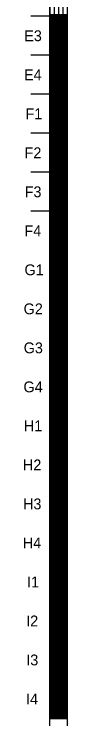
# Model space of a CAD drawing. Extents: x -124 to 80, y -10800 to 19.
# Drawn here: x -120 to 80, y -6482 to -3230 of the extents above; entities that cross this region are included whole.
import ezdxf

# ---------------------------------------------------------------- set-up
doc = ezdxf.new("R2010")
doc.units = 0
for name, color, linetype in [('Scratch_Level_1', 7, 'Continuous'), ('Scratch_Level_3', 7, 'Continuous'), ('Sheet Clip Boundary CELL', 7, 'Continuous')]:
    doc.layers.add(name, color=color, linetype=linetype)

msp = doc.modelspace()

# ---------------------------------------------------------------- linework, layer by layer
at = {"layer": 'Scratch_Level_1'}
for p, q in [((0, 0), (0, -6480)), ((20, 0), (20, -6480)), ((40, 0), (40, -6480)), ((60, 0), (60, -6480)), ((80, 0), (80, -6480)), ((0, -3240), (-88.8, -3240)), ((0, -3232), (80, -3232)), ((0, -3236), (80, -3236)), ((0, -3240), (80, -3240)), ((0, -3244), (80, -3244)), ((0, -3248), (80, -3248)), ((0, -3252), (80, -3252)), ((0, -3256), (80, -3256)), ((0, -3260), (80, -3260)), ((0, -3264), (80, -3264)), ((0, -3268), (80, -3268)), ((0, -3272), (80, -3272)), ((0, -3276), (80, -3276)), ((0, -3280), (80, -3280)), ((0, -3284), (80, -3284)), ((0, -3288), (80, -3288)), ((0, -3292), (80, -3292)), ((0, -3296), (80, -3296)), ((0, -3300), (80, -3300)), ((0, -3304), (80, -3304)), ((0, -3308), (80, -3308)), ((0, -3312), (80, -3312)), ((0, -3316), (80, -3316)), ((0, -3320), (80, -3320)), ((0, -3324), (80, -3324)), ((0, -3328), (80, -3328)), ((0, -3332), (80, -3332)), ((0, -3336), (80, -3336)), ((0, -3340), (80, -3340)), ((0, -3344), (80, -3344)), ((0, -3348), (80, -3348)), ((0, -3352), (80, -3352)), ((0, -3356), (80, -3356)), ((0, -3360), (80, -3360)), ((0, -3364), (80, -3364)), ((0, -3368), (80, -3368)), ((0, -3372), (80, -3372)), ((0, -3376), (80, -3376)), ((0, -3380), (80, -3380)), ((0, -3384), (80, -3384)), ((0, -3388), (80, -3388)), ((0, -3392), (80, -3392)), ((0, -3396), (80, -3396)), ((0, -3400), (80, -3400)), ((0, -3404), (80, -3404)), ((0, -3408), (80, -3408)), ((0, -3412), (80, -3412)), ((0, -3420), (-88.8, -3420)), ((0, -3416), (80, -3416)), ((0, -3420), (80, -3420)), ((0, -3424), (80, -3424)), ((0, -3428), (80, -3428)), ((0, -3432), (80, -3432)), ((0, -3436), (80, -3436)), ((0, -3440), (80, -3440)), ((0, -3444), (80, -3444)), ((0, -3448), (80, -3448)), ((0, -3452), (80, -3452)), ((0, -3456), (80, -3456)), ((0, -3460), (80, -3460)), ((0, -3464), (80, -3464)), ((0, -3468), (80, -3468)), ((0, -3472), (80, -3472)), ((0, -3476), (80, -3476)), ((0, -3480), (80, -3480)), ((0, -3484), (80, -3484)), ((0, -3488), (80, -3488)), ((0, -3492), (80, -3492)), ((0, -3496), (80, -3496)), ((0, -3500), (80, -3500)), ((0, -3504), (80, -3504)), ((0, -3508), (80, -3508)), ((0, -3512), (80, -3512)), ((0, -3516), (80, -3516)), ((0, -3520), (80, -3520)), ((0, -3524), (80, -3524)), ((0, -3528), (80, -3528)), ((0, -3532), (80, -3532)), ((0, -3536), (80, -3536)), ((0, -3540), (80, -3540)), ((0, -3544), (80, -3544)), ((0, -3548), (80, -3548)), ((0, -3552), (80, -3552)), ((0, -3556), (80, -3556)), ((0, -3560), (80, -3560)), ((0, -3564), (80, -3564)), ((0, -3568), (80, -3568)), ((0, -3572), (80, -3572)), ((0, -3576), (80, -3576)), ((0, -3600), (-88.8, -3600)), ((0, -3580), (80, -3580)), ((0, -3584), (80, -3584)), ((0, -3588), (80, -3588)), ((0, -3592), (80, -3592)), ((0, -3596), (80, -3596)), ((0, -3600), (80, -3600)), ((0, -3604), (80, -3604)), ((0, -3608), (80, -3608)), ((0, -3612), (80, -3612)), ((0, -3616), (80, -3616)), ((0, -3620), (80, -3620)), ((0, -3624), (80, -3624)), ((0, -3628), (80, -3628)), ((0, -3632), (80, -3632)), ((0, -3636), (80, -3636)), ((0, -3640), (80, -3640)), ((0, -3644), (80, -3644)), ((0, -3648), (80, -3648)), ((0, -3652), (80, -3652)), ((0, -3656), (80, -3656)), ((0, -3660), (80, -3660)), ((0, -3664), (80, -3664)), ((0, -3668), (80, -3668)), ((0, -3672), (80, -3672)), ((0, -3676), (80, -3676)), ((0, -3680), (80, -3680)), ((0, -3684), (80, -3684)), ((0, -3688), (80, -3688)), ((0, -3692), (80, -3692)), ((0, -3696), (80, -3696)), ((0, -3700), (80, -3700)), ((0, -3704), (80, -3704)), ((0, -3708), (80, -3708)), ((0, -3712), (80, -3712)), ((0, -3716), (80, -3716)), ((0, -3720), (80, -3720)), ((0, -3724), (80, -3724)), ((0, -3728), (80, -3728)), ((0, -3732), (80, -3732)), ((0, -3736), (80, -3736)), ((0, -3740), (80, -3740)), ((0, -3744), (80, -3744)), ((0, -3748), (80, -3748)), ((0, -3752), (80, -3752)), ((0, -3756), (80, -3756)), ((0, -3760), (80, -3760)), ((0, -3764), (80, -3764)), ((0, -3768), (80, -3768)), ((0, -3772), (80, -3772)), ((0, -3780), (-88.8, -3780)), ((0, -3776), (80, -3776)), ((0, -3780), (80, -3780)), ((0, -3784), (80, -3784)), ((0, -3788), (80, -3788)), ((0, -3792), (80, -3792)), ((0, -3796), (80, -3796)), ((0, -3800), (80, -3800)), ((0, -3804), (80, -3804)), ((0, -3808), (80, -3808)), ((0, -3812), (80, -3812)), ((0, -3816), (80, -3816)), ((0, -3820), (80, -3820)), ((0, -3824), (80, -3824)), ((0, -3828), (80, -3828)), ((0, -3832), (80, -3832)), ((0, -3836), (80, -3836)), ((0, -3840), (80, -3840)), ((0, -3844), (80, -3844)), ((0, -3848), (80, -3848)), ((0, -3852), (80, -3852)), ((0, -3856), (80, -3856)), ((0, -3860), (80, -3860)), ((0, -3864), (80, -3864)), ((0, -3868), (80, -3868)), ((0, -3872), (80, -3872)), ((0, -3876), (80, -3876)), ((0, -3880), (80, -3880)), ((0, -3884), (80, -3884)), ((0, -3888), (80, -3888)), ((0, -3892), (80, -3892)), ((0, -3896), (80, -3896)), ((0, -3900), (80, -3900)), ((0, -3904), (80, -3904)), ((0, -3908), (80, -3908)), ((0, -3912), (80, -3912)), ((0, -3916), (80, -3916)), ((0, -3920), (80, -3920)), ((0, -3924), (80, -3924)), ((0, -3928), (80, -3928)), ((0, -3932), (80, -3932)), ((0, -3960), (-88.8, -3960)), ((0, -3936), (80, -3936)), ((0, -3940), (80, -3940)), ((0, -3944), (80, -3944)), ((0, -3948), (80, -3948)), ((0, -3952), (80, -3952)), ((0, -3956), (80, -3956)), ((0, -3960), (80, -3960)), ((0, -3964), (80, -3964)), ((0, -3968), (80, -3968)), ((0, -3972), (80, -3972)), ((0, -3976), (80, -3976)), ((0, -3980), (80, -3980)), ((0, -3984), (80, -3984)), ((0, -3988), (80, -3988)), ((0, -3992), (80, -3992)), ((0, -3996), (80, -3996)), ((0, -4000), (80, -4000)), ((0, -4004), (80, -4004)), ((0, -4008), (80, -4008)), ((0, -4012), (80, -4012)), ((0, -4016), (80, -4016)), ((0, -4020), (80, -4020)), ((0, -4024), (80, -4024)), ((0, -4028), (80, -4028)), ((0, -4032), (80, -4032)), ((0, -4036), (80, -4036)), ((0, -4040), (80, -4040)), ((0, -4044), (80, -4044)), ((0, -4048), (80, -4048)), ((0, -4052), (80, -4052)), ((0, -4056), (80, -4056)), ((0, -4060), (80, -4060)), ((0, -4064), (80, -4064)), ((0, -4068), (80, -4068)), ((0, -4072), (80, -4072)), ((0, -4076), (80, -4076)), ((0, -4080), (80, -4080)), ((0, -4084), (80, -4084)), ((0, -4088), (80, -4088)), ((0, -4092), (80, -4092)), ((0, -4096), (80, -4096)), ((0, -4100), (80, -4100)), ((0, -4104), (80, -4104)), ((0, -4108), (80, -4108)), ((0, -4112), (80, -4112)), ((0, -4116), (80, -4116)), ((0, -4120), (80, -4120)), ((0, -4124), (80, -4124)), ((0, -4128), (80, -4128)), ((0, -4140), (-88.8, -4140)), ((0, -4132), (80, -4132)), ((0, -4136), (80, -4136)), ((0, -4140), (80, -4140)), ((0, -4144), (80, -4144)), ((0, -4148), (80, -4148)), ((0, -4152), (80, -4152)), ((0, -4156), (80, -4156)), ((0, -4160), (80, -4160)), ((0, -4164), (80, -4164)), ((0, -4168), (80, -4168)), ((0, -4172), (80, -4172)), ((0, -4176), (80, -4176)), ((0, -4180), (80, -4180)), ((0, -4184), (80, -4184)), ((0, -4188), (80, -4188)), ((0, -4192), (80, -4192)), ((0, -4196), (80, -4196)), ((0, -4200), (80, -4200)), ((0, -4204), (80, -4204)), ((0, -4208), (80, -4208)), ((0, -4212), (80, -4212)), ((0, -4216), (80, -4216)), ((0, -4220), (80, -4220)), ((0, -4224), (80, -4224)), ((0, -4228), (80, -4228)), ((0, -4232), (80, -4232)), ((0, -4236), (80, -4236)), ((0, -4240), (80, -4240)), ((0, -4244), (80, -4244)), ((0, -4248), (80, -4248)), ((0, -4252), (80, -4252)), ((0, -4256), (80, -4256)), ((0, -4260), (80, -4260)), ((0, -4264), (80, -4264)), ((0, -4268), (80, -4268)), ((0, -4272), (80, -4272)), ((0, -4276), (80, -4276)), ((0, -4280), (80, -4280)), ((0, -4284), (80, -4284)), ((0, -4288), (80, -4288)), ((0, -4292), (80, -4292)), ((0, -4296), (80, -4296)), ((0, -4300), (80, -4300)), ((0, -4304), (80, -4304)), ((0, -4308), (80, -4308)), ((0, -4312), (80, -4312)), ((0, -4316), (80, -4316)), ((0, -4320), (80, -4320)), ((0, -4324), (80, -4324)), ((0, -4328), (80, -4328)), ((0, -4332), (80, -4332)), ((0, -4336), (80, -4336)), ((0, -4340), (80, -4340)), ((0, -4344), (80, -4344)), ((0, -4348), (80, -4348)), ((0, -4352), (80, -4352)), ((0, -4356), (80, -4356)), ((0, -4360), (80, -4360)), ((0, -4364), (80, -4364)), ((0, -4368), (80, -4368)), ((0, -4372), (80, -4372)), ((0, -4376), (80, -4376)), ((0, -4380), (80, -4380)), ((0, -4384), (80, -4384)), ((0, -4388), (80, -4388)), ((0, -4392), (80, -4392)), ((0, -4396), (80, -4396)), ((0, -4400), (80, -4400)), ((0, -4404), (80, -4404)), ((0, -4408), (80, -4408)), ((0, -4412), (80, -4412)), ((0, -4416), (80, -4416)), ((0, -4420), (80, -4420)), ((0, -4424), (80, -4424)), ((0, -4428), (80, -4428)), ((0, -4432), (80, -4432)), ((0, -4436), (80, -4436)), ((0, -4440), (80, -4440)), ((0, -4444), (80, -4444)), ((0, -4448), (80, -4448)), ((0, -4452), (80, -4452)), ((0, -4456), (80, -4456)), ((0, -4460), (80, -4460)), ((0, -4464), (80, -4464)), ((0, -4468), (80, -4468)), ((0, -4472), (80, -4472)), ((0, -4476), (80, -4476)), ((0, -4480), (80, -4480)), ((0, -4484), (80, -4484)), ((0, -4488), (80, -4488)), ((0, -4492), (80, -4492)), ((0, -4496), (80, -4496)), ((0, -4500), (80, -4500)), ((0, -4504), (80, -4504)), ((0, -4508), (80, -4508)), ((0, -4512), (80, -4512)), ((0, -4516), (80, -4516)), ((0, -4520), (80, -4520)), ((0, -4524), (80, -4524)), ((0, -4528), (80, -4528)), ((0, -4532), (80, -4532)), ((0, -4536), (80, -4536)), ((0, -4540), (80, -4540)), ((0, -4544), (80, -4544)), ((0, -4548), (80, -4548)), ((0, -4552), (80, -4552)), ((0, -4556), (80, -4556)), ((0, -4560), (80, -4560)), ((0, -4564), (80, -4564)), ((0, -4568), (80, -4568)), ((0, -4572), (80, -4572)), ((0, -4576), (80, -4576)), ((0, -4580), (80, -4580)), ((0, -4584), (80, -4584)), ((0, -4588), (80, -4588)), ((0, -4592), (80, -4592)), ((0, -4596), (80, -4596)), ((0, -4600), (80, -4600)), ((0, -4604), (80, -4604)), ((0, -4608), (80, -4608)), ((0, -4612), (80, -4612)), ((0, -4616), (80, -4616)), ((0, -4620), (80, -4620)), ((0, -4624), (80, -4624)), ((0, -4628), (80, -4628)), ((0, -4632), (80, -4632)), ((0, -4636), (80, -4636)), ((0, -4640), (80, -4640)), ((0, -4644), (80, -4644)), ((0, -4648), (80, -4648)), ((0, -4652), (80, -4652)), ((0, -4656), (80, -4656)), ((0, -4660), (80, -4660)), ((0, -4664), (80, -4664)), ((0, -4668), (80, -4668)), ((0, -4672), (80, -4672)), ((0, -4676), (80, -4676)), ((0, -4680), (80, -4680)), ((0, -4684), (80, -4684)), ((0, -4688), (80, -4688)), ((0, -4692), (80, -4692)), ((0, -4696), (80, -4696)), ((0, -4700), (80, -4700)), ((0, -4704), (80, -4704)), ((0, -4708), (80, -4708)), ((0, -4712), (80, -4712)), ((0, -4716), (80, -4716)), ((0, -4720), (80, -4720)), ((0, -4724), (80, -4724)), ((0, -4728), (80, -4728)), ((0, -4732), (80, -4732)), ((0, -4736), (80, -4736)), ((0, -4740), (80, -4740)), ((0, -4744), (80, -4744)), ((0, -4748), (80, -4748)), ((0, -4752), (80, -4752)), ((0, -4756), (80, -4756)), ((0, -4760), (80, -4760)), ((0, -4764), (80, -4764)), ((0, -4768), (80, -4768)), ((0, -4772), (80, -4772)), ((0, -4776), (80, -4776)), ((0, -4780), (80, -4780)), ((0, -4784), (80, -4784)), ((0, -4788), (80, -4788)), ((0, -4792), (80, -4792)), ((0, -4796), (80, -4796)), ((0, -4800), (80, -4800)), ((0, -4804), (80, -4804)), ((0, -4808), (80, -4808)), ((0, -4812), (80, -4812)), ((0, -4816), (80, -4816)), ((0, -4820), (80, -4820)), ((0, -4824), (80, -4824)), ((0, -4828), (80, -4828)), ((0, -4832), (80, -4832)), ((0, -4836), (80, -4836)), ((0, -4840), (80, -4840)), ((0, -4844), (80, -4844)), ((0, -4848), (80, -4848)), ((0, -4852), (80, -4852)), ((0, -4856), (80, -4856)), ((0, -4860), (80, -4860)), ((0, -4864), (80, -4864)), ((0, -4868), (80, -4868)), ((0, -4872), (80, -4872)), ((0, -4876), (80, -4876)), ((0, -4880), (80, -4880)), ((0, -4884), (80, -4884)), ((0, -4888), (80, -4888)), ((0, -4892), (80, -4892)), ((0, -4896), (80, -4896)), ((0, -4900), (80, -4900)), ((0, -4904), (80, -4904)), ((0, -4908), (80, -4908)), ((0, -4912), (80, -4912)), ((0, -4916), (80, -4916)), ((0, -4920), (80, -4920)), ((0, -4924), (80, -4924)), ((0, -4928), (80, -4928)), ((0, -4932), (80, -4932)), ((0, -4936), (80, -4936)), ((0, -4940), (80, -4940)), ((0, -4944), (80, -4944)), ((0, -4948), (80, -4948)), ((0, -4952), (80, -4952)), ((0, -4956), (80, -4956)), ((0, -4960), (80, -4960)), ((0, -4964), (80, -4964)), ((0, -4968), (80, -4968)), ((0, -4972), (80, -4972)), ((0, -4976), (80, -4976)), ((0, -4980), (80, -4980)), ((0, -4984), (80, -4984)), ((0, -4988), (80, -4988)), ((0, -4992), (80, -4992)), ((0, -4996), (80, -4996)), ((0, -5000), (80, -5000)), ((0, -5004), (80, -5004)), ((0, -5008), (80, -5008)), ((0, -5012), (80, -5012)), ((0, -5016), (80, -5016)), ((0, -5020), (80, -5020)), ((0, -5024), (80, -5024)), ((0, -5028), (80, -5028)), ((0, -5032), (80, -5032)), ((0, -5036), (80, -5036)), ((0, -5040), (80, -5040)), ((0, -5044), (80, -5044)), ((0, -5048), (80, -5048)), ((0, -5052), (80, -5052)), ((0, -5056), (80, -5056)), ((0, -5060), (80, -5060)), ((0, -5064), (80, -5064)), ((0, -5068), (80, -5068)), ((0, -5072), (80, -5072)), ((0, -5076), (80, -5076)), ((0, -5080), (80, -5080)), ((0, -5084), (80, -5084)), ((0, -5088), (80, -5088)), ((0, -5092), (80, -5092)), ((0, -5096), (80, -5096)), ((0, -5100), (80, -5100)), ((0, -5104), (80, -5104)), ((0, -5108), (80, -5108)), ((0, -5112), (80, -5112)), ((0, -5116), (80, -5116)), ((0, -5120), (80, -5120)), ((0, -5124), (80, -5124)), ((0, -5128), (80, -5128)), ((0, -5132), (80, -5132)), ((0, -5136), (80, -5136)), ((0, -5140), (80, -5140)), ((0, -5144), (80, -5144)), ((0, -5148), (80, -5148)), ((0, -5152), (80, -5152)), ((0, -5156), (80, -5156)), ((0, -5160), (80, -5160)), ((0, -5164), (80, -5164)), ((0, -5168), (80, -5168)), ((0, -5172), (80, -5172)), ((0, -5176), (80, -5176)), ((0, -5180), (80, -5180)), ((0, -5184), (80, -5184)), ((0, -5188), (80, -5188)), ((0, -5192), (80, -5192)), ((0, -5196), (80, -5196)), ((0, -5200), (80, -5200)), ((0, -5204), (80, -5204)), ((0, -5208), (80, -5208)), ((0, -5212), (80, -5212)), ((0, -5216), (80, -5216)), ((0, -5220), (80, -5220)), ((0, -5224), (80, -5224)), ((0, -5228), (80, -5228)), ((0, -5232), (80, -5232)), ((0, -5236), (80, -5236)), ((0, -5240), (80, -5240)), ((0, -5244), (80, -5244)), ((0, -5248), (80, -5248)), ((0, -5252), (80, -5252)), ((0, -5256), (80, -5256)), ((0, -5260), (80, -5260)), ((0, -5264), (80, -5264)), ((0, -5268), (80, -5268)), ((0, -5272), (80, -5272)), ((0, -5276), (80, -5276)), ((0, -5280), (80, -5280)), ((0, -5284), (80, -5284)), ((0, -5288), (80, -5288)), ((0, -5292), (80, -5292)), ((0, -5296), (80, -5296)), ((0, -5300), (80, -5300)), ((0, -5304), (80, -5304)), ((0, -5308), (80, -5308)), ((0, -5312), (80, -5312)), ((0, -5316), (80, -5316)), ((0, -5320), (80, -5320)), ((0, -5324), (80, -5324)), ((0, -5328), (80, -5328)), ((0, -5332), (80, -5332)), ((0, -5336), (80, -5336)), ((0, -5340), (80, -5340)), ((0, -5344), (80, -5344)), ((0, -5348), (80, -5348)), ((0, -5352), (80, -5352)), ((0, -5356), (80, -5356)), ((0, -5360), (80, -5360)), ((0, -5364), (80, -5364)), ((0, -5368), (80, -5368)), ((0, -5372), (80, -5372)), ((0, -5376), (80, -5376)), ((0, -5380), (80, -5380)), ((0, -5384), (80, -5384)), ((0, -5388), (80, -5388)), ((0, -5392), (80, -5392)), ((0, -5396), (80, -5396)), ((0, -5400), (80, -5400)), ((0, -5404), (80, -5404)), ((0, -5408), (80, -5408)), ((0, -5412), (80, -5412)), ((0, -5416), (80, -5416)), ((0, -5420), (80, -5420)), ((0, -5424), (80, -5424)), ((0, -5428), (80, -5428)), ((0, -5432), (80, -5432)), ((0, -5436), (80, -5436)), ((0, -5440), (80, -5440)), ((0, -5444), (80, -5444)), ((0, -5448), (80, -5448)), ((0, -5452), (80, -5452)), ((0, -5456), (80, -5456)), ((0, -5460), (80, -5460)), ((0, -5464), (80, -5464)), ((0, -5468), (80, -5468)), ((0, -5472), (80, -5472)), ((0, -5476), (80, -5476)), ((0, -5480), (80, -5480)), ((0, -5484), (80, -5484)), ((0, -5488), (80, -5488)), ((0, -5492), (80, -5492)), ((0, -5496), (80, -5496)), ((0, -5500), (80, -5500)), ((0, -5504), (80, -5504)), ((0, -5508), (80, -5508)), ((0, -5512), (80, -5512)), ((0, -5516), (80, -5516)), ((0, -5520), (80, -5520)), ((0, -5524), (80, -5524)), ((0, -5528), (80, -5528)), ((0, -5532), (80, -5532)), ((0, -5536), (80, -5536)), ((0, -5540), (80, -5540)), ((0, -5544), (80, -5544)), ((0, -5548), (80, -5548)), ((0, -5552), (80, -5552)), ((0, -5556), (80, -5556)), ((0, -5560), (80, -5560)), ((0, -5564), (80, -5564)), ((0, -5568), (80, -5568)), ((0, -5572), (80, -5572)), ((0, -5576), (80, -5576)), ((0, -5580), (80, -5580)), ((0, -5584), (80, -5584)), ((0, -5588), (80, -5588)), ((0, -5592), (80, -5592)), ((0, -5596), (80, -5596)), ((0, -5600), (80, -5600)), ((0, -5604), (80, -5604)), ((0, -5608), (80, -5608)), ((0, -5612), (80, -5612)), ((0, -5616), (80, -5616)), ((0, -5620), (80, -5620)), ((0, -5624), (80, -5624)), ((0, -5628), (80, -5628)), ((0, -5632), (80, -5632)), ((0, -5636), (80, -5636)), ((0, -5640), (80, -5640)), ((0, -5644), (80, -5644)), ((0, -5648), (80, -5648)), ((0, -5652), (80, -5652)), ((0, -5656), (80, -5656)), ((0, -5660), (80, -5660)), ((0, -5664), (80, -5664)), ((0, -5668), (80, -5668)), ((0, -5672), (80, -5672)), ((0, -5676), (80, -5676)), ((0, -5680), (80, -5680)), ((0, -5684), (80, -5684)), ((0, -5688), (80, -5688)), ((0, -5692), (80, -5692)), ((0, -5696), (80, -5696)), ((0, -5700), (80, -5700)), ((0, -5704), (80, -5704)), ((0, -5708), (80, -5708)), ((0, -5712), (80, -5712)), ((0, -5716), (80, -5716)), ((0, -5720), (80, -5720)), ((0, -5724), (80, -5724)), ((0, -5728), (80, -5728)), ((0, -5732), (80, -5732)), ((0, -5736), (80, -5736)), ((0, -5740), (80, -5740)), ((0, -5744), (80, -5744)), ((0, -5748), (80, -5748)), ((0, -5752), (80, -5752)), ((0, -5756), (80, -5756)), ((0, -5760), (80, -5760)), ((0, -5764), (80, -5764)), ((0, -5768), (80, -5768)), ((0, -5772), (80, -5772)), ((0, -5776), (80, -5776)), ((0, -5780), (80, -5780)), ((0, -5784), (80, -5784)), ((0, -5788), (80, -5788)), ((0, -5792), (80, -5792)), ((0, -5796), (80, -5796)), ((0, -5800), (80, -5800)), ((0, -5804), (80, -5804)), ((0, -5808), (80, -5808)), ((0, -5812), (80, -5812)), ((0, -5816), (80, -5816)), ((0, -5820), (80, -5820)), ((0, -5824), (80, -5824)), ((0, -5828), (80, -5828)), ((0, -5832), (80, -5832)), ((0, -5836), (80, -5836)), ((0, -5840), (80, -5840)), ((0, -5844), (80, -5844)), ((0, -5848), (80, -5848)), ((0, -5852), (80, -5852)), ((0, -5856), (80, -5856)), ((0, -5860), (80, -5860)), ((0, -5864), (80, -5864)), ((0, -5868), (80, -5868)), ((0, -5872), (80, -5872)), ((0, -5876), (80, -5876)), ((0, -5880), (80, -5880)), ((0, -5884), (80, -5884)), ((0, -5888), (80, -5888)), ((0, -5892), (80, -5892)), ((0, -5896), (80, -5896)), ((0, -5900), (80, -5900)), ((0, -5904), (80, -5904)), ((0, -5908), (80, -5908)), ((0, -5912), (80, -5912)), ((0, -5916), (80, -5916)), ((0, -5920), (80, -5920)), ((0, -5924), (80, -5924)), ((0, -5928), (80, -5928)), ((0, -5932), (80, -5932)), ((0, -5936), (80, -5936)), ((0, -5940), (80, -5940)), ((0, -5944), (80, -5944)), ((0, -5948), (80, -5948)), ((0, -5952), (80, -5952)), ((0, -5956), (80, -5956)), ((0, -5960), (80, -5960)), ((0, -5964), (80, -5964)), ((0, -5968), (80, -5968)), ((0, -5972), (80, -5972)), ((0, -5976), (80, -5976)), ((0, -5980), (80, -5980)), ((0, -5984), (80, -5984)), ((0, -5988), (80, -5988)), ((0, -5992), (80, -5992)), ((0, -5996), (80, -5996)), ((0, -6000), (80, -6000)), ((0, -6004), (80, -6004)), ((0, -6008), (80, -6008)), ((0, -6012), (80, -6012)), ((0, -6016), (80, -6016)), ((0, -6020), (80, -6020)), ((0, -6024), (80, -6024)), ((0, -6028), (80, -6028)), ((0, -6032), (80, -6032)), ((0, -6036), (80, -6036)), ((0, -6040), (80, -6040)), ((0, -6044), (80, -6044)), ((0, -6048), (80, -6048)), ((0, -6052), (80, -6052)), ((0, -6056), (80, -6056)), ((0, -6060), (80, -6060)), ((0, -6064), (80, -6064)), ((0, -6068), (80, -6068)), ((0, -6072), (80, -6072)), ((0, -6076), (80, -6076)), ((0, -6080), (80, -6080)), ((0, -6084), (80, -6084)), ((0, -6088), (80, -6088)), ((0, -6092), (80, -6092)), ((0, -6096), (80, -6096)), ((0, -6100), (80, -6100)), ((0, -6104), (80, -6104)), ((0, -6108), (80, -6108)), ((0, -6112), (80, -6112)), ((0, -6116), (80, -6116)), ((0, -6120), (80, -6120)), ((0, -6124), (80, -6124)), ((0, -6128), (80, -6128)), ((0, -6132), (80, -6132)), ((0, -6136), (80, -6136)), ((0, -6140), (80, -6140)), ((0, -6144), (80, -6144)), ((0, -6148), (80, -6148)), ((0, -6152), (80, -6152)), ((0, -6156), (80, -6156)), ((0, -6160), (80, -6160)), ((0, -6164), (80, -6164)), ((0, -6168), (80, -6168)), ((0, -6172), (80, -6172)), ((0, -6176), (80, -6176)), ((0, -6180), (80, -6180)), ((0, -6184), (80, -6184)), ((0, -6188), (80, -6188)), ((0, -6192), (80, -6192)), ((0, -6196), (80, -6196)), ((0, -6200), (80, -6200)), ((0, -6204), (80, -6204)), ((0, -6208), (80, -6208)), ((0, -6212), (80, -6212)), ((0, -6216), (80, -6216)), ((0, -6220), (80, -6220)), ((0, -6224), (80, -6224)), ((0, -6228), (80, -6228)), ((0, -6232), (80, -6232)), ((0, -6236), (80, -6236)), ((0, -6240), (80, -6240)), ((0, -6244), (80, -6244)), ((0, -6248), (80, -6248)), ((0, -6252), (80, -6252)), ((0, -6256), (80, -6256)), ((0, -6260), (80, -6260)), ((0, -6264), (80, -6264)), ((0, -6268), (80, -6268)), ((0, -6272), (80, -6272)), ((0, -6276), (80, -6276)), ((0, -6280), (80, -6280)), ((0, -6284), (80, -6284)), ((0, -6288), (80, -6288)), ((0, -6292), (80, -6292)), ((0, -6296), (80, -6296)), ((0, -6300), (80, -6300)), ((0, -6304), (80, -6304)), ((0, -6308), (80, -6308)), ((0, -6312), (80, -6312)), ((0, -6316), (80, -6316)), ((0, -6320), (80, -6320)), ((0, -6324), (80, -6324)), ((0, -6328), (80, -6328)), ((0, -6332), (80, -6332)), ((0, -6336), (80, -6336)), ((0, -6340), (80, -6340)), ((0, -6344), (80, -6344)), ((0, -6348), (80, -6348)), ((0, -6352), (80, -6352)), ((0, -6356), (80, -6356)), ((0, -6360), (80, -6360)), ((0, -6364), (80, -6364)), ((0, -6368), (80, -6368)), ((0, -6372), (80, -6372)), ((0, -6376), (80, -6376)), ((0, -6380), (80, -6380)), ((0, -6384), (80, -6384)), ((0, -6388), (80, -6388)), ((0, -6392), (80, -6392)), ((0, -6396), (80, -6396)), ((0, -6400), (80, -6400)), ((0, -6404), (80, -6404)), ((0, -6408), (80, -6408)), ((0, -6412), (80, -6412)), ((0, -6416), (80, -6416)), ((0, -6420), (80, -6420)), ((0, -6424), (80, -6424)), ((0, -6428), (80, -6428)), ((0, -6432), (80, -6432)), ((0, -6436), (80, -6436)), ((0, -6440), (80, -6440)), ((0, -6444), (80, -6444)), ((0, -6448), (80, -6448)), ((0, -6452), (80, -6452)), ((0, -6456), (80, -6456)), ((0, -6460), (80, -6460)), ((0, -6464), (80, -6464)), ((0, -6468), (80, -6468)), ((0, -6472), (80, -6472)), ((0, -6476), (80, -6476)), ((0, -6480), (80, -6480)), ((0, -6480), (80, -6480))]:
    msp.add_line(p, q, dxfattribs=at)
at = {"layer": 'Sheet Clip Boundary CELL'}
for points in [[(0, -3060), (80, -3060), (80, -3240), (0, -3240)], [(0, -3240), (80, -3240), (80, -3420), (0, -3420)], [(0, -3420), (80, -3420), (80, -3600), (0, -3600)], [(0, -3600), (80, -3600), (80, -3780), (0, -3780)], [(0, -3780), (80, -3780), (80, -3960), (0, -3960)], [(0, -3960), (80, -3960), (80, -4140), (0, -4140)], [(0, -4140), (80, -4140), (80, -4320), (0, -4320)], [(0, -4320), (80, -4320), (80, -4500), (0, -4500)], [(0, -4500), (80, -4500), (80, -4680), (0, -4680)], [(0, -4680), (80, -4680), (80, -4860), (0, -4860)], [(0, -4860), (80, -4860), (80, -5040), (0, -5040)], [(0, -5040), (80, -5040), (80, -5220), (0, -5220)], [(0, -5220), (80, -5220), (80, -5400), (0, -5400)], [(0, -5400), (80, -5400), (80, -5580), (0, -5580)], [(0, -5580), (80, -5580), (80, -5760), (0, -5760)], [(0, -5760), (80, -5760), (80, -5940), (0, -5940)], [(0, -5940), (80, -5940), (80, -6120), (0, -6120)], [(0, -6120), (80, -6120), (80, -6300), (0, -6300)], [(0, -6300), (80, -6300), (80, -6480), (0, -6480)], [(0, -6480), (80, -6480), (80, -6660), (0, -6660)]]:
    msp.add_lwpolyline(points, close=True, dxfattribs=at)

# ---------------------------------------------------------------- texts
at = {"layer": 'Scratch_Level_3'}
for s, p in [('E3', (-118.8, -3355)), ('E4', (-119.8, -3535)), ('F1', (-113.1, -3715)), ('F2', (-117.2, -3895)), ('F3', (-116.8, -4075)), ('F4', (-117.9, -4255)), ('G1', (-117.5, -4435)), ('G2', (-121.7, -4615)), ('G3', (-121.3, -4795)), ('G4', (-122.3, -4975)), ('H1', (-120.7, -5155)), ('H2', (-124.9, -5335)), ('H3', (-124.5, -5515)), ('H4', (-125.5, -5695)), ('I1', (-105.6, -5875)), ('I2', (-109.8, -6055)), ('I3', (-109.4, -6235)), ('I4', (-110.4, -6415))]:
    msp.add_text(s, height=50, dxfattribs=at).set_placement(p)

doc.saveas('drawing.dxf')
